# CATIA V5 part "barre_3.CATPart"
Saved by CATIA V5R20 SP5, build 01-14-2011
Part number: barre_3
Publications: "diamètre pivot en F", "diamètre pivot en D"
Bounding box of the stored display mesh (mm): x 0 to 12, y -87.539 to 6, z 53.045 to 138
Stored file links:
  M:\EU_thinkMotion\IAO_2010\iao\IAO_MMS_Groupe2\IAO_MMS_Groupe2\sdubois\sdubois\sdubois\IAO_mecanisme\barre_3.CATPart
  M:\EU_thinkMotion\IAO_2010\iao\IAO_MMS_Groupe2\IAO_MMS_Groupe2\sdubois\sdubois\sdubois\IAO_mecanisme\assembage final.CATProduct
  M:\EU_thinkMotion\IAO_2010\iao\IAO_MMS_Groupe2\IAO_MMS_Groupe2\sdubois\sdubois\sdubois\IAO_mecanisme\squelette_3.CATPart
  M:\EU_thinkMotion\IAO_2010\iao\IAO_MMS_Groupe2\IAO_MMS_Groupe2\sdubois\sdubois\sdubois\IAO_mecanisme\bati_0.CATPart
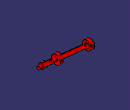
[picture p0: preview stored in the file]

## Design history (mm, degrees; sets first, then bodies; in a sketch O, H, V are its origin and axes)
Parameters
  `diamètre pivot en F` = 6 mm
  `diamètre pivot en D` = 8 mm
External parameters (linked from other documents)
  External.largeur_barre = 6 mm
  `External.diamètre pivot en C` = 6 mm
Set1
  Plane1 to Plane4: linked copy from another document
  Point1 to Point5: linked copy from another document
  DatumSurface1: linked copy from another document
Body1 (main body)
  Sketch1 on Plane1, origin (0, 0, 0), H (0, 1, 0), V (0, 0, 1)
    line L1 (-84.5378, 60.2826) -> (-3.9987, 132.2372)
    point P1 (-84.5378, 60.2826)
    point P2 (-3.9987, 132.2372)
    reference intersected line E1 through (-52.341, 85.0247) direction (-0.7457, -0.6662) from Plane2
    line L2 (-80.5403, 55.8082) -> (-0.0013, 127.7628)
    point P3 (-80.5403, 55.8082)
    point P4 (-0.0013, 127.7628)
    reference intersected line E2 through (-52.341, 85.0247) direction (-0.7457, -0.6662) from Plane2
    reference intersected line E3 through (72.031, 47.1369) direction (-0.6662, 0.7457) from Plane3
    reference intersected line E4 through (72.031, 47.1369) direction (-0.6662, 0.7457) from Plane3
    reference intersected line E5 through (-20.6227, -11.2578) direction (-0.6662, 0.7457) from Plane4
    reference intersected line E6 through (-20.6227, -11.2578) direction (-0.6662, 0.7457) from Plane4
    reference projected point E7 (-59.1829, 82.935) from Point1
    reference projected point E8 (-55.1854, 78.4606) from Point2
    line L3 (-3.9987, 132.2372) -> (-0.0013, 127.7628)
    point P5 (-3.9987, 132.2372)
    point P6 (-0.0013, 127.7628)
    line L4 (-84.5378, 60.2826) -> (-80.5403, 55.8082)
    point P7 (-84.5378, 60.2826)
    point P8 (-80.5403, 55.8082)
    distance P4 E3 = 0
    distance P2 E4 = 0
    distance P1 E5 = 0
    distance P3 E6 = 0
    distance L1 E7 = 0
    distance L2 E8 = 0
    distance P2 P5 = 0
    distance P6 P4 = 0
    distance P1 P7 = 0
    distance P8 P3 = 0
    parallelism: L1 E1, L2 E2
  Sketch2 on Plane1, origin (0, 0, 0), H (0, 1, 0), V (0, 0, 1)
    circle A1 centre (-57.1842, 80.6978) radius 8
    point P1 (-57.1842, 80.6978)
    reference projected point E1 (-57.1842, 80.6978) from Point3
    distance P1 E1 = 0
    radius A1 = 8
  Sketch3 on Plane1, origin (0, 0, 0), H (0, 1, 0), V (0, 0, 1)
    circle A1 centre (-2, 130) radius 8
    point P1 (-2, 130)
    reference projected point E1 (-2, 130) from Point4
    distance P1 E1 = 0
    radius A1 = 8
  Sketch4 on Plane1, origin (0, 0, 0), H (0, 1, 0), V (0, 0, 1)
    circle A1 centre (-82.5391, 58.0454) radius 5
    point P1 (-82.5391, 58.0454)
    reference projected point E1 (-82.5391, 58.0454) from Point5
    distance P1 E1 = 0
    radius A1 = 5
  Sketch5 on Plane1, origin (0, 0, 0), H (0, 1, 0), V (0, 0, 1)
    circle A1 centre (-2, 130) radius 4
    point P1 (-2, 130)
    reference projected point E1 (-2, 130) from Point4
    distance E1 P1 = 0
    radius A1 = 4 {= `diamètre pivot en D` /2}
  Sketch6 on Plane1, origin (0, 0, 0), H (0, 1, 0), V (0, 0, 1)
    circle A1 centre (-57.1842, 80.6978) radius 3
    point P1 (-57.1842, 80.6978)
    reference projected point E1 (-57.1842, 80.6978) from Point3
    distance P1 E1 = 0
    radius A1 = 3 {= `diamètre pivot en F` /2}
  Sketch7 on Plane1, origin (0, 0, 0), H (0, 1, 0), V (0, 0, 1)
    circle A1 centre (-82.5391, 58.0454) radius 3
    point P1 (-82.5391, 58.0454)
    reference projected point E1 (-82.5391, 58.0454) from Point5
    distance E1 P1 = 0
    radius A1 = 3 {= `External.diamètre pivot en C` /2}
  Pad1: profile Sketch1, direction (1, 0, 0), length 6 {= External.largeur_barre}, opposite side up to face of DatumSurface1
  Pad2: profile Sketch3, direction (1, 0, 0), length 6 {= External.largeur_barre}, opposite side up to face of DatumSurface1
  Pad3: profile Sketch2, direction (1, 0, 0), length 6 {= External.largeur_barre}, opposite side up to face of DatumSurface1
  Pad4: profile Sketch4, direction (1, 0, 0), length 6 {= External.largeur_barre}, opposite side up to face of DatumSurface1
  Pad5: profile Sketch7, direction (1, 0, 0), length 12 {= 2*External.largeur_barre}, opposite side up to face of DatumSurface1
  Pad6: profile Sketch6, direction (1, 0, 0), length 12 {= 2*External.largeur_barre}, opposite side up to face of DatumSurface1
  Pocket1: profile Sketch5, direction (1, 0, 0), length 6 {= External.largeur_barre}, opposite side up to face of DatumSurface1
